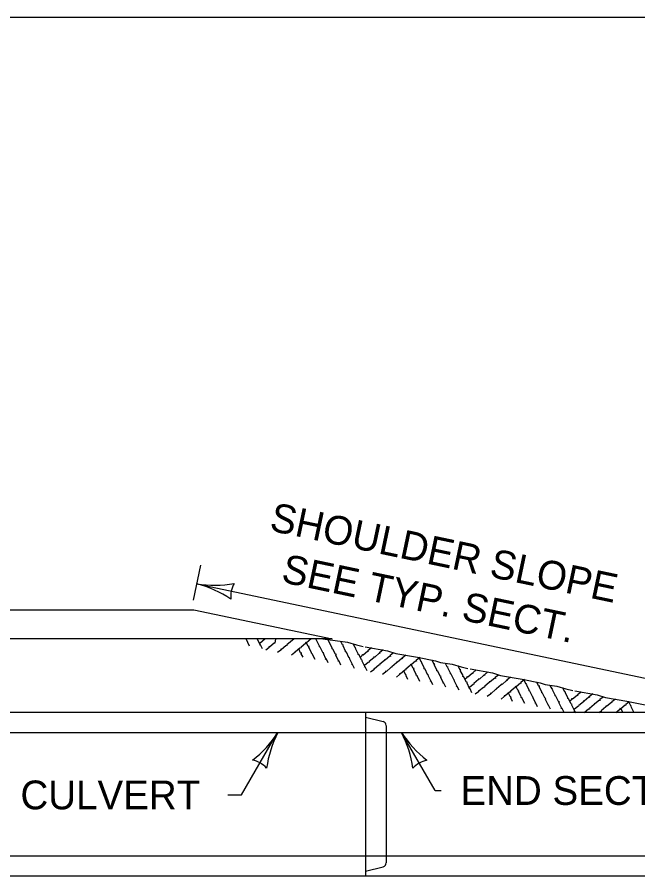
# Model space of a CAD drawing. Extents: x 49991.4 to 50022.1, y 49985 to 50011.4.
# Drawn here: x 50004.56 to 50005.853, y 49997.203 to 49998.999 of the extents above; entities that cross this region are included whole.
import ezdxf

# ---------------------------------------------------------------- set-up
doc = ezdxf.new("R2010")
doc.units = 0
for name, color, linetype in [('Level 1', 7, 'Continuous'), ('Level 2', 7, 'Continuous'), ('Level 3', 7, 'Continuous'), ('Level 4', 7, 'Continuous')]:
    doc.layers.add(name, color=color, linetype=linetype)

msp = doc.modelspace()

# ---------------------------------------------------------------- linework, layer by layer
at = {"layer": 'Level 1'}
for p, q in [((50003.702, 49997.7636), (50004.9281, 49997.7636)), ((50004.9281, 49997.7636), (50005.2161, 49997.7029)), ((50005.2161, 49997.7029), (50003.7019, 49997.7029)), ((50003.702, 49997.5504), (50005.9421, 49997.5504)), ((50005.2857, 49997.5504), (50005.2857, 49997.208)), ((50006.3273, 49997.208), (50003.702, 49997.208))]:
    msp.add_line(p, q, dxfattribs=at)
msp.add_lwpolyline([(49999.3835, 49998.9992), (50016.7501, 49998.9992), (50016.7501, 49987.7988), (49999.3835, 49987.7988)], close=True, dxfattribs=at)
for points in [[(50005.044, 49997.6876), (50005.0367, 49997.7029)], [(50005.0707, 49997.6822), (50005.0668, 49997.6904), (50005.065, 49997.6902), (50005.0657, 49997.6916), (50005.0601, 49997.7029)], [(50005.0762, 49997.7029), (50005.0653, 49997.6936)], [(50005.0978, 49997.7029), (50005.0969, 49997.6942), (50005.095, 49997.694), (50005.086, 49997.6862), (50005.0842, 49997.6865), (50005.0842, 49997.6846), (50005.0776, 49997.6793)], [(50005.1365, 49997.7029), (50005.1219, 49997.691), (50005.1214, 49997.6892), (50005.1197, 49997.6889), (50005.1106, 49997.6812), (50005.1089, 49997.6814), (50005.1089, 49997.6796), (50005.1023, 49997.6745)], [(50005.172, 49997.7029), (50005.1625, 49997.695), (50005.1607, 49997.6955), (50005.1604, 49997.6936), (50005.1511, 49997.6859), (50005.1508, 49997.6841), (50005.1489, 49997.6838), (50005.1399, 49997.6762), (50005.1379, 49997.6763), (50005.1379, 49997.6745), (50005.1316, 49997.6692)], [(50005.1808, 49997.6598), (50005.1745, 49997.6722), (50005.1729, 49997.673), (50005.173, 49997.6746), (50005.1676, 49997.6853), (50005.1682, 49997.6871), (50005.1663, 49997.6874), (50005.1628, 49997.6949)], [(50005.2075, 49997.6532), (50005.2039, 49997.6606), (50005.2024, 49997.6604), (50005.203, 49997.6618), (50005.1976, 49997.6724), (50005.1983, 49997.6742), (50005.1967, 49997.6746), (50005.1913, 49997.6858), (50005.1895, 49997.6865), (50005.1898, 49997.6882), (50005.1822, 49997.7029)], [(50005.1968, 49997.7029), (50005.2479, 49997.6961), (50005.2665, 49997.691), (50005.2807, 49997.6871)], [(50005.2343, 49997.6482), (50005.2303, 49997.6565), (50005.2288, 49997.6565), (50005.2293, 49997.6577), (50005.2239, 49997.6685), (50005.2247, 49997.6703), (50005.2229, 49997.6709), (50005.2174, 49997.6817), (50005.2157, 49997.6826), (50005.2159, 49997.6844), (50005.2064, 49997.7029)], [(50005.2623, 49997.6416), (50005.2583, 49997.6499), (50005.2569, 49997.6499), (50005.2575, 49997.6512), (50005.2519, 49997.6619), (50005.2528, 49997.6636), (50005.251, 49997.6642), (50005.2456, 49997.6752), (50005.2439, 49997.676), (50005.2441, 49997.6776), (50005.2387, 49997.6883), (50005.2393, 49997.6901), (50005.2375, 49997.6904), (50005.2337, 49997.6979)], [(50005.1555, 49997.6646), (50005.1514, 49997.6722), (50005.1523, 49997.6739), (50005.1503, 49997.6742), (50005.1466, 49997.682)], [(50005.2769, 49997.6595), (50005.2719, 49997.6697), (50005.2702, 49997.6706), (50005.2703, 49997.6722), (50005.2648, 49997.6829), (50005.2654, 49997.6846), (50005.2636, 49997.685), (50005.2599, 49997.6928)], [(50005.2979, 49997.6841), (50005.2906, 49997.6782), (50005.2909, 49997.6768), (50005.2894, 49997.6769), (50005.2803, 49997.6692), (50005.2793, 49997.6694)], [(50005.3223, 49997.68), (50005.3149, 49997.6742), (50005.3153, 49997.6726), (50005.3139, 49997.673), (50005.3047, 49997.6652), (50005.3027, 49997.6656), (50005.3027, 49997.6637), (50005.2933, 49997.656), (50005.2929, 49997.6542), (50005.2912, 49997.6541), (50005.2834, 49997.6476)], [(50005.2849, 49997.6862), (50005.3314, 49997.6784), (50005.3485, 49997.6727), (50005.3935, 49997.6649), (50005.4313, 49997.6572), (50005.4413, 49997.6536), (50005.4661, 49997.65), (50005.4847, 49997.6451), (50005.4989, 49997.6412)], [(50005.2792, 49997.6696), (50005.2783, 49997.6697), (50005.278, 49997.6679), (50005.2747, 49997.6649)], [(50005.2889, 49997.6362), (50005.2849, 49997.6445), (50005.2834, 49997.6442), (50005.284, 49997.6457), (50005.2786, 49997.6565), (50005.2793, 49997.6582), (50005.2777, 49997.6588), (50005.2773, 49997.6595)], [(50005.3439, 49997.6738), (50005.3371, 49997.6682), (50005.3374, 49997.6666), (50005.3362, 49997.667), (50005.3269, 49997.6592), (50005.3251, 49997.6596), (50005.3249, 49997.6577), (50005.3155, 49997.65), (50005.3149, 49997.6482), (50005.3133, 49997.6481), (50005.3043, 49997.6403), (50005.3025, 49997.6406), (50005.3025, 49997.6386), (50005.2959, 49997.6334)], [(50005.3693, 49997.6692), (50005.3619, 49997.6632), (50005.3623, 49997.6618), (50005.3609, 49997.662), (50005.3518, 49997.6542), (50005.3499, 49997.6547), (50005.3497, 49997.6529), (50005.3401, 49997.6451), (50005.3398, 49997.6433), (50005.338, 49997.6432), (50005.3289, 49997.6352), (50005.3272, 49997.6356), (50005.3272, 49997.6337), (50005.3206, 49997.6286)], [(50005.3983, 49997.664), (50005.3909, 49997.6582), (50005.3914, 49997.6565), (50005.3899, 49997.6568), (50005.3807, 49997.6492), (50005.3789, 49997.6496), (50005.3788, 49997.6476), (50005.3693, 49997.64), (50005.3689, 49997.638), (50005.3671, 49997.6379), (50005.3581, 49997.6302), (50005.3563, 49997.6304), (50005.3563, 49997.6286), (50005.3499, 49997.6232)], [(50005.4257, 49997.6073), (50005.4223, 49997.6146), (50005.4208, 49997.6145), (50005.4213, 49997.6157), (50005.4159, 49997.6265), (50005.4166, 49997.6283), (50005.4149, 49997.6289), (50005.4094, 49997.6397), (50005.4077, 49997.6406), (50005.4079, 49997.6424), (50005.4025, 49997.6529), (50005.4031, 49997.6546), (50005.4015, 49997.6552), (50005.3977, 49997.6626)], [(50005.4526, 49997.6022), (50005.4487, 49997.6106), (50005.4469, 49997.6106), (50005.4475, 49997.6118), (50005.4421, 49997.6226), (50005.443, 49997.6244), (50005.4412, 49997.625), (50005.4358, 49997.6358), (50005.4343, 49997.6366), (50005.4343, 49997.6385), (50005.4287, 49997.649), (50005.4295, 49997.6506), (50005.4277, 49997.6512), (50005.4241, 49997.6588)], [(50005.3989, 49997.6139), (50005.3927, 49997.6262), (50005.3911, 49997.6271), (50005.3913, 49997.6289), (50005.3859, 49997.6394), (50005.3865, 49997.641), (50005.3845, 49997.6416), (50005.3812, 49997.649)], [(50005.4808, 49997.5958), (50005.4766, 49997.604), (50005.4751, 49997.604), (50005.4757, 49997.6052), (50005.4703, 49997.616), (50005.4709, 49997.6176), (50005.4693, 49997.6182), (50005.4639, 49997.6292), (50005.4622, 49997.6301), (50005.4623, 49997.6318), (50005.4569, 49997.6424), (50005.4574, 49997.644), (50005.4557, 49997.6445), (50005.452, 49997.652)], [(50005.4952, 49997.6136), (50005.4901, 49997.6238), (50005.4885, 49997.6246), (50005.4886, 49997.6265), (50005.4829, 49997.637), (50005.4838, 49997.6386), (50005.4819, 49997.6392), (50005.4781, 49997.6469)], [(50005.5033, 49997.6403), (50005.5498, 49997.6325), (50005.5667, 49997.6268), (50005.6117, 49997.619), (50005.6494, 49997.6112), (50005.6596, 49997.6078), (50005.6843, 49997.6043), (50005.7029, 49997.599), (50005.7172, 49997.5953)], [(50005.3737, 49997.6187), (50005.3698, 49997.6262), (50005.3704, 49997.628), (50005.3686, 49997.6286), (50005.365, 49997.6361)], [(50005.4975, 49997.6236), (50005.4964, 49997.6238), (50005.4964, 49997.622), (50005.4929, 49997.6192)], [(50005.5162, 49997.6382), (50005.5089, 49997.6322), (50005.5093, 49997.6307), (50005.5078, 49997.6312), (50005.4985, 49997.6232), (50005.4976, 49997.6236)], [(50005.5405, 49997.6342), (50005.5333, 49997.6283), (50005.5336, 49997.6268), (50005.5321, 49997.6271), (50005.5229, 49997.6193), (50005.521, 49997.6198), (50005.521, 49997.6181), (50005.5114, 49997.6102), (50005.5111, 49997.6085), (50005.5095, 49997.608), (50005.5019, 49997.6018)], [(50005.5623, 49997.6277), (50005.5555, 49997.6223), (50005.5559, 49997.6208), (50005.5545, 49997.6211), (50005.5453, 49997.6133), (50005.5433, 49997.6138), (50005.5432, 49997.6118), (50005.5337, 49997.6042), (50005.5335, 49997.6022), (50005.5315, 49997.602), (50005.5225, 49997.5944), (50005.5207, 49997.5946), (50005.5207, 49997.5928), (50005.5141, 49997.5875)], [(50005.5876, 49997.6232), (50005.5801, 49997.6172), (50005.5804, 49997.6157), (50005.5792, 49997.6162), (50005.5699, 49997.6082), (50005.5681, 49997.6088), (50005.5679, 49997.607), (50005.5583, 49997.599), (50005.5579, 49997.5974), (50005.5563, 49997.5972), (50005.5473, 49997.5893), (50005.5455, 49997.5898), (50005.5455, 49997.5878), (50005.5389, 49997.5826)], [(50005.5072, 49997.5905), (50005.5033, 49997.5986), (50005.5018, 49997.5986), (50005.5023, 49997.5998), (50005.4969, 49997.6106), (50005.4976, 49997.6122), (50005.4959, 49997.6127), (50005.4955, 49997.6136)], [(50005.6164, 49997.6181), (50005.6093, 49997.6122), (50005.6098, 49997.6108), (50005.6083, 49997.6109), (50005.599, 49997.6032), (50005.5972, 49997.6036), (50005.5969, 49997.6018), (50005.5876, 49997.5941), (50005.5873, 49997.5922), (50005.5855, 49997.592), (50005.5763, 49997.5842), (50005.5744, 49997.5845), (50005.5744, 49997.5826), (50005.5681, 49997.5776)], [(50005.644, 49997.5614), (50005.6404, 49997.5688), (50005.6389, 49997.5688), (50005.6395, 49997.5701), (50005.6341, 49997.5808), (50005.635, 49997.5824), (50005.6332, 49997.583), (50005.6278, 49997.5938), (50005.6263, 49997.5947), (50005.6263, 49997.5965), (50005.6207, 49997.6072), (50005.6213, 49997.6088), (50005.6197, 49997.6092), (50005.6159, 49997.6168)], [(50005.6709, 49997.5563), (50005.6669, 49997.5647), (50005.6653, 49997.5647), (50005.6657, 49997.5659), (50005.6605, 49997.5767), (50005.6613, 49997.5785), (50005.6595, 49997.5791), (50005.6542, 49997.5899), (50005.6524, 49997.5906), (50005.6524, 49997.5926), (50005.647, 49997.6031), (50005.6477, 49997.6049), (50005.6459, 49997.6052), (50005.6423, 49997.6127)], [(50005.6989, 49997.5497), (50005.695, 49997.5581), (50005.6933, 49997.5581), (50005.6939, 49997.5593), (50005.6884, 49997.5701), (50005.6893, 49997.5719), (50005.6875, 49997.5722), (50005.6821, 49997.5833), (50005.6806, 49997.584), (50005.6806, 49997.5857), (50005.6752, 49997.5965), (50005.6759, 49997.5982), (50005.674, 49997.5986), (50005.6704, 49997.6061)], [(50005.5919, 49997.5728), (50005.5879, 49997.5803), (50005.5888, 49997.5821), (50005.5869, 49997.5826), (50005.5833, 49997.59)], [(50005.6173, 49997.568), (50005.611, 49997.5803), (50005.6093, 49997.5812), (50005.6095, 49997.583), (50005.6041, 49997.5936), (50005.6047, 49997.5953), (50005.6029, 49997.5958), (50005.5995, 49997.6031)], [(50005.7135, 49997.5676), (50005.7083, 49997.5779), (50005.7067, 49997.5786), (50005.7069, 49997.5806), (50005.7015, 49997.5911), (50005.7019, 49997.5928), (50005.7001, 49997.5932), (50005.6963, 49997.6012)], [(50005.7345, 49997.5923), (50005.7271, 49997.5866), (50005.7274, 49997.5851), (50005.7262, 49997.5852), (50005.7167, 49997.5776), (50005.7159, 49997.5778)], [(50005.7587, 49997.5882), (50005.7514, 49997.5824), (50005.7519, 49997.5809), (50005.7505, 49997.5812), (50005.7412, 49997.5734), (50005.7393, 49997.5737), (50005.7393, 49997.572), (50005.7298, 49997.5642), (50005.7293, 49997.5626), (50005.7277, 49997.5622), (50005.7199, 49997.5557)], [(50005.7214, 49997.5944), (50005.7679, 49997.5866), (50005.785, 49997.5809), (50005.83, 49997.5731), (50005.8678, 49997.5653), (50005.8779, 49997.5617), (50005.9026, 49997.5584), (50005.9212, 49997.5532), (50005.9355, 49997.5494)], [(50005.7157, 49997.5778), (50005.7148, 49997.5779), (50005.7148, 49997.5761), (50005.7112, 49997.5732)], [(50005.7233, 49997.5486), (50005.7214, 49997.5526), (50005.7199, 49997.5526), (50005.7205, 49997.5539), (50005.7151, 49997.5646), (50005.7159, 49997.5662), (50005.7142, 49997.5668), (50005.7137, 49997.5676)], [(50005.7805, 49997.5818), (50005.7737, 49997.5764), (50005.7742, 49997.5749), (50005.7727, 49997.575), (50005.7634, 49997.5674), (50005.7616, 49997.5677), (50005.7615, 49997.566), (50005.752, 49997.5582), (50005.7517, 49997.5566), (50005.7497, 49997.5562), (50005.7412, 49997.5486)], [(50005.8059, 49997.5773), (50005.7983, 49997.5716), (50005.7988, 49997.5701), (50005.7975, 49997.5702), (50005.7883, 49997.5626), (50005.7863, 49997.5629), (50005.7862, 49997.5611), (50005.7766, 49997.5533), (50005.7765, 49997.5515), (50005.7745, 49997.5512), (50005.7715, 49997.5486)], [(50005.8348, 49997.572), (50005.8276, 49997.5662), (50005.8279, 49997.5647), (50005.8264, 49997.565), (50005.8173, 49997.5572), (50005.8155, 49997.5576), (50005.8153, 49997.556), (50005.8066, 49997.5486)], [(50005.8444, 49997.5486), (50005.8443, 49997.5488), (50005.8444, 49997.5506), (50005.839, 49997.5612), (50005.8397, 49997.5629), (50005.8379, 49997.5632), (50005.8343, 49997.5707)], [(50005.8228, 49997.5486), (50005.8229, 49997.5494), (50005.8213, 49997.5497), (50005.8177, 49997.557)]]:
    msp.add_lwpolyline(points, dxfattribs=at)
at = {"layer": 'Level 3'}
for p, q in [((50004.927, 49997.7841), (50004.9422, 49997.8569)), ((50004.934, 49997.8178), (50005.9533, 49997.6033)), ((50005.0269, 49997.3777), (50005.1022, 49997.5079)), ((50005.4303, 49997.3869), (50005.3606, 49997.5077)), ((50004.9987, 49997.3777), (50005.0269, 49997.3777)), ((50005.4303, 49997.3869), (50005.4432, 49997.3869))]:
    msp.add_line(p, q, dxfattribs=at)
for centre, radius, start, end in [((50004.9706, 49998.0479), 0.233, 260.9753, 280.2252), ((50004.8795, 49997.6023), 0.2223, 55.604, 75.7875), ((50005.0595, 49997.7915), 0.0548, 150.2868, 186.0092), ((50004.9153, 49997.627), 0.2223, 307.4112, 327.5947), ((50005.3102, 49997.4013), 0.233, 152.7825, 172.0323), ((50005.1636, 49997.4046), 0.2223, 7.435, 27.6185), ((50005.5565, 49997.6339), 0.233, 212.8063, 232.0561), ((50005.0388, 49997.3969), 0.0548, 42.094, 77.8163), ((50005.4247, 49997.3966), 0.0548, 102.1178, 137.8401)]:
    msp.add_arc(centre, radius, start, end, dxfattribs=at)
at = {"layer": 'Level 4'}
for p, q in [((50005.2857, 49997.5397), (50005.3221, 49997.5305)), ((50005.3286, 49997.5221), (50005.3286, 49997.2363)), ((50003.702, 49997.5077), (50005.9483, 49997.5077)), ((50003.702, 49997.2508), (50006.3273, 49997.2508)), ((50005.2857, 49997.2188), (50005.3221, 49997.2279))]:
    msp.add_line(p, q, dxfattribs=at)
for centre, start, end in [((50005.32, 49997.5222), 0, 75.8703), ((50005.32, 49997.2362), 284.1107, 0)]:
    msp.add_arc(centre, 0.00856, start, end, dxfattribs=at)

# ---------------------------------------------------------------- texts
at = {"layer": 'Level 2'}
for s, p in [('SHOULDER SLOPE', (50005.0833, 49997.9293)), ('SEE TYP. SECT.', (50005.1079, 49997.8219))]:
    msp.add_text(s, height=0.06, rotation=348.1237, dxfattribs=at).set_placement(p)
for s, p in [('CULVERT', (50004.5667, 49997.3477)), ('END SECTION', (50005.4832, 49997.3569))]:
    msp.add_text(s, height=0.06, dxfattribs=at).set_placement(p)

doc.saveas('drawing.dxf')
